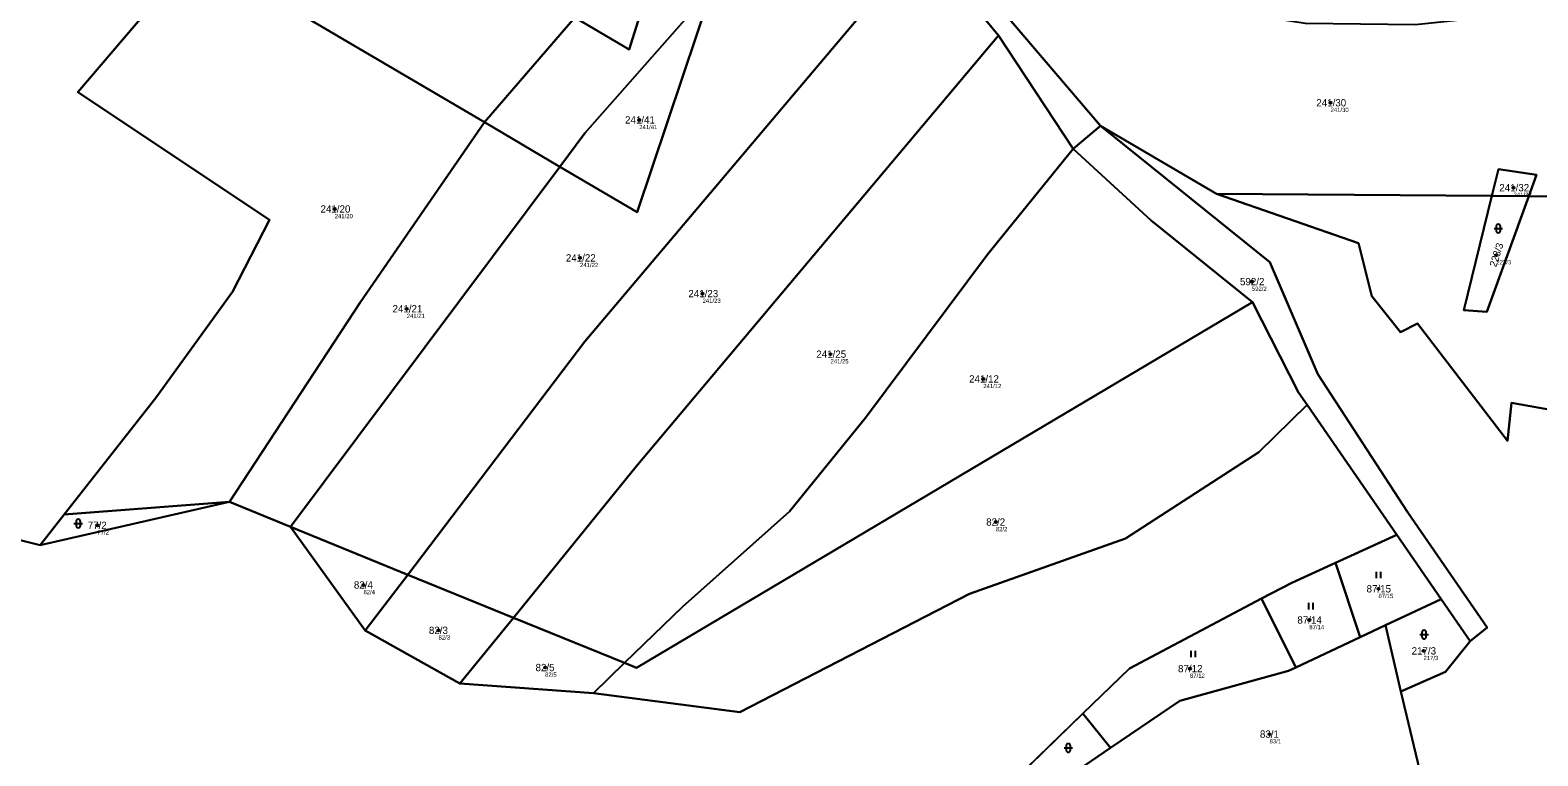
# Model space of a CAD drawing. Extents: x -766177 to -763254, y -1057727 to -1053915.
# Drawn here: x -765125.5 to -764774.5, y -1057477.4 to -1057308.4 of the extents above; entities that cross this region are included whole.
import ezdxf

# ---------------------------------------------------------------- set-up
doc = ezdxf.new("R2010")
doc.units = 0
for name, color, linetype in [('Vrstva 1', 7, 'Continuous'), ('Vrstva 2', 7, 'Continuous'), ('Vrstva 3', 7, 'Continuous'), ('Vrstva 50', 7, 'Continuous'), ('Vrstva 51', 7, 'Continuous')]:
    doc.layers.add(name, color=color, linetype=linetype)

msp = doc.modelspace()

# ---------------------------------------------------------------- linework, layer by layer
at = {"layer": 'Vrstva 1'}
for p, q in [((-764876.27, -1057330.63), (-764922.39, -1057276.56)), ((-764900.05, -1057309.6), (-764917.91, -1057287.93)), ((-765086.75, -1057290.32), (-765019.75, -1057329.82)), ((-765019.75, -1057329.82), (-764998.7, -1057305.43)), ((-764882.68, -1057336.02), (-764900.05, -1057309.6)), ((-765002.19, -1057340.18), (-765019.75, -1057329.82)), ((-764882.68, -1057336.02), (-764876.27, -1057330.63)), ((-764849.27, -1057346.5), (-764876.27, -1057330.63)), ((-765064.89, -1057424.12), (-765002.19, -1057340.18)), ((-764785.18, -1057346.97), (-764849.27, -1057346.5)), ((-764776.59, -1057347.03), (-764785.18, -1057346.97)), ((-764807.31, -1057425.97), (-764828.22, -1057395.63)), ((-765123.19, -1057428.35), (-765079.08, -1057418.23)), ((-765079.08, -1057418.23), (-765117.57, -1057421.2)), ((-765064.89, -1057424.12), (-765079.08, -1057418.23)), ((-765117.57, -1057421.2), (-765123.19, -1057428.35)), ((-765064.89, -1057424.12), (-765047.51, -1057448.26)), ((-765037.61, -1057435.23), (-765064.89, -1057424.12)), ((-764821.57, -1057432.45), (-764807.31, -1057425.97)), ((-764797.01, -1057440.9), (-764807.31, -1057425.97)), ((-764815.84, -1057449.77), (-764821.57, -1057432.45)), ((-765037.61, -1057435.23), (-765047.51, -1057448.26)), ((-765012.98, -1057445.26), (-765037.61, -1057435.23)), ((-764830.79, -1057456.83), (-764838.8, -1057440.81)), ((-764809.98, -1057447.01), (-764797.01, -1057440.9)), ((-764790.26, -1057450.69), (-764797.01, -1057440.9)), ((-765025.45, -1057460.61), (-765012.98, -1057445.26)), ((-764987.11, -1057455.79), (-765012.98, -1057445.26)), ((-765047.51, -1057448.26), (-765025.45, -1057460.61)), ((-764815.84, -1057449.77), (-764830.79, -1057456.83)), ((-764809.98, -1057447.01), (-764815.84, -1057449.77)), ((-764806.34, -1057462.41), (-764809.98, -1057447.01)), ((-764994.34, -1057462.8), (-764987.11, -1057455.79)), ((-765025.45, -1057460.61), (-764994.34, -1057462.8)), ((-764801.59, -1057482.52), (-764806.34, -1057462.41)), ((-764903.9, -1057490.42), (-764880.38, -1057467.6)), ((-764880.38, -1057467.6), (-764873.98, -1057475.6)), ((-764873.98, -1057475.6), (-764884.28, -1057482.63))]:
    msp.add_line(p, q, dxfattribs=at)
for points in [[(-764998.7, -1057305.43), (-764986.08, -1057312.85), (-764975.18, -1057278.18)], [(-765037.61, -1057435.23), (-764996.36, -1057380.92), (-764917.91, -1057287.93)], [(-765117.57, -1057421.2), (-765096.23, -1057394.04), (-765078.39, -1057369.34), (-765069.81, -1057352.56), (-765114.44, -1057322.78), (-765086.75, -1057290.32)], [(-764966.7, -1057298.67), (-764984.2, -1057350.79), (-765002.19, -1057340.18)], [(-764966.7, -1057298.67), (-764996.34, -1057332.34), (-765002.19, -1057340.18)], [(-765012.98, -1057445.26), (-764984.38, -1057410.02), (-764900.05, -1057309.6)], [(-765079.08, -1057418.23), (-765048.71, -1057371.8), (-765019.75, -1057329.82)], [(-764876.27, -1057330.63), (-764836.9, -1057362.45), (-764825.69, -1057388.55), (-764804.78, -1057420.77), (-764786.27, -1057447.55), (-764790.26, -1057450.69)], [(-764987.11, -1057455.79), (-764973.65, -1057442.75), (-764948.7, -1057420.51), (-764931.04, -1057398.68), (-764902.6, -1057360.62), (-764882.68, -1057336.02)], [(-764882.68, -1057336.02), (-764864.48, -1057352.68), (-764840.93, -1057371.77)], [(-764785.18, -1057346.97), (-764783.65, -1057340.72), (-764774.8, -1057342.1), (-764776.59, -1057347.03)], [(-764755.4, -1057399.73), (-764780.63, -1057395.22), (-764781.54, -1057404.07), (-764802.49, -1057376.7), (-764806.46, -1057378.71), (-764813.12, -1057370.35), (-764816.27, -1057358), (-764849.27, -1057346.5)], [(-764776.59, -1057347.03), (-764786.38, -1057374.02), (-764791.71, -1057373.58), (-764785.18, -1057346.97)], [(-764739.69, -1057350.49), (-764743.65, -1057347.27), (-764776.59, -1057347.03)], [(-764840.93, -1057371.77), (-764984.31, -1057456.93), (-764987.11, -1057455.79)], [(-764840.93, -1057371.77), (-764830.2, -1057392.76), (-764828.22, -1057395.63)], [(-765123.19, -1057428.35), (-765142.95, -1057423.38), (-765198.86, -1057384.72)], [(-764828.22, -1057395.63), (-764839.45, -1057406.67), (-764870.48, -1057426.83), (-764906.81, -1057439.73), (-764960.27, -1057467.29), (-764994.34, -1057462.8)], [(-764838.8, -1057440.81), (-764831.78, -1057437.09), (-764821.57, -1057432.45)], [(-764880.38, -1057467.6), (-764869.56, -1057457.1), (-764838.8, -1057440.81)], [(-764790.26, -1057450.69), (-764795.98, -1057457.9), (-764806.34, -1057462.41)], [(-764830.79, -1057456.83), (-764832.51, -1057457.64), (-764857.84, -1057464.6), (-764873.98, -1057475.6)]]:
    msp.add_lwpolyline(points, dxfattribs=at)
at = {"layer": 'Vrstva 3'}
for p, q in [((-764784.681, -1057354.581), (-764782.679, -1057354.581)), ((-764784.181, -1057354.081), (-764784.181, -1057355.082)), ((-764783.179, -1057355.082), (-764783.179, -1057354.081)), ((-765115.311, -1057423.301), (-765113.309, -1057423.301)), ((-765114.811, -1057422.801), (-765114.811, -1057423.802)), ((-765113.809, -1057423.802), (-765113.809, -1057422.801)), ((-764812.011, -1057436.04), (-764812.011, -1057434.54)), ((-764811.01, -1057436.04), (-764811.01, -1057434.54)), ((-764827.821, -1057443.32), (-764827.821, -1057441.82)), ((-764826.82, -1057443.32), (-764826.82, -1057441.82)), ((-764801.961, -1057449.191), (-764799.959, -1057449.191)), ((-764801.461, -1057448.691), (-764801.461, -1057449.692)), ((-764800.459, -1057449.692), (-764800.459, -1057448.691)), ((-764855.171, -1057454.48), (-764855.171, -1057452.98)), ((-764854.17, -1057454.48), (-764854.17, -1057452.98)), ((-764884.801, -1057475.601), (-764882.799, -1057475.601)), ((-764884.301, -1057475.101), (-764884.301, -1057476.102)), ((-764883.299, -1057476.102), (-764883.299, -1057475.101))]:
    msp.add_line(p, q, dxfattribs=at)
for centre, start, end in [((-764783.68, -1057354.0809), 0, 180), ((-764783.68, -1057355.0809), 180, 359.9878861), ((-765114.31, -1057422.8009), 0, 180), ((-765114.31, -1057423.8009), 180, 359.9878861), ((-764800.96, -1057448.6909), 0, 180), ((-764800.96, -1057449.6909), 180, 359.9878861), ((-764883.8, -1057475.1009), 0, 180), ((-764883.8, -1057476.1009), 180, 359.9878861)]:
    msp.add_arc(centre, 0.5, start, end, dxfattribs=at)
at = {"layer": 'Vrstva 50'}
for centre in [(-764822.75, -1057325.27994), (-764983.7, -1057329.27994), (-764780.14, -1057345.06994), (-765054.6, -1057350.02994), (-764997.48, -1057361.41994), (-764784.14, -1057360.77994), (-764968.96, -1057369.74994), (-764841.05, -1057366.94994), (-765037.84, -1057373.27994), (-764939.17, -1057383.84994), (-764903.6, -1057389.61994), (-765109.87, -1057423.72994), (-764900.68, -1057422.95994), (-765047.9, -1057437.61994), (-764811.58, -1057438.51994), (-764827.69, -1057445.78994), (-765030.43, -1057448.19994), (-764801.09, -1057452.97994), (-765005.61, -1057456.85994), (-764855.48, -1057457.10994), (-764836.94, -1057472.36994)]:
    msp.add_circle(centre, 0.25, dxfattribs=at)
at = {"layer": 'Vrstva 51'}
for points in [[(-764951.49, -1057253.35), (-764937.29, -1057265.26), (-764917.91, -1057287.93), (-764900.05, -1057309.6), (-764882.68, -1057336.02), (-764876.27, -1057330.63), (-764922.39, -1057276.56), (-764933.09, -1057264.01), (-764950.28, -1057249.75)], [(-764951.49, -1057253.35), (-764952.56, -1057252.46), (-764975.18, -1057278.18), (-764986.08, -1057312.85), (-764998.7, -1057305.43), (-765019.75, -1057329.82), (-765002.19, -1057340.18), (-764996.34, -1057332.34), (-764966.7, -1057298.67)], [(-765086.75, -1057290.32), (-765019.75, -1057329.82), (-764998.7, -1057305.43), (-765065.93, -1057265.91)], [(-764996.36, -1057380.92), (-764917.91, -1057287.93), (-764937.29, -1057265.26), (-764966.7, -1057298.67), (-764984.2, -1057350.79), (-765002.19, -1057340.18), (-765064.89, -1057424.12), (-765037.61, -1057435.23)], [(-765078.39, -1057369.34), (-765069.81, -1057352.56), (-765114.44, -1057322.78), (-765086.75, -1057290.32), (-765118.25, -1057271.74), (-765150.88, -1057311.82), (-765192.69, -1057371.46), (-765198.86, -1057384.72), (-765142.95, -1057423.38), (-765123.19, -1057428.35), (-765117.57, -1057421.2), (-765096.23, -1057394.04)], [(-764986.08, -1057312.85), (-764975.18, -1057278.18), (-764998.7, -1057305.43)], [(-764755.14, -1057302.1), (-764802.96, -1057307.13), (-764828.56, -1057306.85), (-764848.07, -1057303.89), (-764887.78, -1057292.31), (-764922.39, -1057276.56), (-764876.27, -1057330.63), (-764849.27, -1057346.5), (-764785.18, -1057346.97), (-764783.65, -1057340.72), (-764774.8, -1057342.1), (-764776.59, -1057347.03), (-764743.65, -1057347.27), (-764739.69, -1057350.49), (-764747.15, -1057333.46)], [(-764900.05, -1057309.6), (-764917.91, -1057287.93), (-764996.36, -1057380.92), (-765037.61, -1057435.23), (-765012.98, -1057445.26), (-764984.38, -1057410.02)], [(-765048.71, -1057371.8), (-765019.75, -1057329.82), (-765086.75, -1057290.32), (-765114.44, -1057322.78), (-765069.81, -1057352.56), (-765078.39, -1057369.34), (-765096.23, -1057394.04), (-765117.57, -1057421.2), (-765079.08, -1057418.23)], [(-764996.34, -1057332.34), (-765002.19, -1057340.18), (-764984.2, -1057350.79), (-764966.7, -1057298.67)], [(-764948.7, -1057420.51), (-764931.04, -1057398.68), (-764902.6, -1057360.62), (-764882.68, -1057336.02), (-764900.05, -1057309.6), (-764984.38, -1057410.02), (-765012.98, -1057445.26), (-764987.11, -1057455.79), (-764973.65, -1057442.75)], [(-765002.19, -1057340.18), (-765019.75, -1057329.82), (-765048.71, -1057371.8), (-765079.08, -1057418.23), (-765064.89, -1057424.12)], [(-764840.93, -1057371.77), (-764830.2, -1057392.76), (-764828.22, -1057395.63), (-764807.31, -1057425.97), (-764797.01, -1057440.9), (-764790.26, -1057450.69), (-764786.27, -1057447.55), (-764804.78, -1057420.77), (-764825.69, -1057388.55), (-764836.9, -1057362.45), (-764876.27, -1057330.63), (-764882.68, -1057336.02), (-764864.48, -1057352.68)], [(-764882.68, -1057336.02), (-764902.6, -1057360.62), (-764931.04, -1057398.68), (-764948.7, -1057420.51), (-764973.65, -1057442.75), (-764987.11, -1057455.79), (-764984.31, -1057456.93), (-764840.93, -1057371.77), (-764864.48, -1057352.68)], [(-764785.18, -1057346.97), (-764776.59, -1057347.03), (-764774.8, -1057342.1), (-764783.65, -1057340.72)], [(-764732.1, -1057381.53), (-764735, -1057361.74), (-764739.69, -1057350.49), (-764743.65, -1057347.27), (-764776.59, -1057347.03), (-764786.38, -1057374.02), (-764791.71, -1057373.58), (-764785.18, -1057346.97), (-764849.27, -1057346.5), (-764816.27, -1057358), (-764813.12, -1057370.35), (-764806.46, -1057378.71), (-764802.49, -1057376.7), (-764781.54, -1057404.07), (-764780.63, -1057395.22), (-764755.4, -1057399.73), (-764754.5, -1057378.44)], [(-764776.59, -1057347.03), (-764785.18, -1057346.97), (-764791.71, -1057373.58), (-764786.38, -1057374.02)], [(-764984.31, -1057456.93), (-764987.11, -1057455.79), (-764994.34, -1057462.8), (-764960.27, -1057467.29), (-764906.81, -1057439.73), (-764870.48, -1057426.83), (-764839.45, -1057406.67), (-764828.22, -1057395.63), (-764830.2, -1057392.76), (-764840.93, -1057371.77)], [(-765079.08, -1057418.23), (-765117.57, -1057421.2), (-765123.19, -1057428.35)], [(-765037.61, -1057435.23), (-765064.89, -1057424.12), (-765047.51, -1057448.26)], [(-764807.31, -1057425.97), (-764821.57, -1057432.45), (-764815.84, -1057449.77), (-764809.98, -1057447.01), (-764797.01, -1057440.9)], [(-764815.84, -1057449.77), (-764821.57, -1057432.45), (-764831.78, -1057437.09), (-764838.8, -1057440.81), (-764830.79, -1057456.83)], [(-765012.98, -1057445.26), (-765037.61, -1057435.23), (-765047.51, -1057448.26), (-765025.45, -1057460.61)], [(-764830.79, -1057456.83), (-764838.8, -1057440.81), (-764869.56, -1057457.1), (-764880.38, -1057467.6), (-764873.98, -1057475.6), (-764857.84, -1057464.6), (-764832.51, -1057457.64)], [(-764797.01, -1057440.9), (-764809.98, -1057447.01), (-764806.34, -1057462.41), (-764795.98, -1057457.9), (-764790.26, -1057450.69)], [(-764987.11, -1057455.79), (-765012.98, -1057445.26), (-765025.45, -1057460.61), (-764994.34, -1057462.8)], [(-764873.98, -1057475.6), (-764884.28, -1057482.63), (-764881.69, -1057492.12), (-764851.45, -1057486.26), (-764801.59, -1057482.52), (-764806.34, -1057462.41), (-764809.98, -1057447.01), (-764815.84, -1057449.77), (-764830.79, -1057456.83), (-764832.51, -1057457.64), (-764857.84, -1057464.6)], [(-764884.28, -1057482.63), (-764873.98, -1057475.6), (-764880.38, -1057467.6), (-764903.9, -1057490.42)]]:
    msp.add_lwpolyline(points, close=True, dxfattribs=at)
for points in [[(-764755.4, -1057399.73), (-764780.63, -1057395.22), (-764781.54, -1057404.07), (-764802.49, -1057376.7), (-764806.46, -1057378.71), (-764813.12, -1057370.35), (-764816.27, -1057358), (-764849.27, -1057346.5), (-764876.27, -1057330.63), (-764836.9, -1057362.45), (-764825.69, -1057388.55), (-764804.78, -1057420.77), (-764786.27, -1057447.55), (-764790.26, -1057450.69), (-764795.98, -1057457.9), (-764806.34, -1057462.41), (-764801.59, -1057482.52)], [(-764903.9, -1057490.42), (-764880.38, -1057467.6), (-764869.56, -1057457.1), (-764838.8, -1057440.81), (-764831.78, -1057437.09), (-764821.57, -1057432.45), (-764807.31, -1057425.97), (-764828.22, -1057395.63), (-764839.45, -1057406.67), (-764870.48, -1057426.83), (-764906.81, -1057439.73), (-764960.27, -1057467.29), (-764994.34, -1057462.8), (-765025.45, -1057460.61), (-765047.51, -1057448.26), (-765064.89, -1057424.12), (-765079.08, -1057418.23), (-765123.19, -1057428.35), (-765142.95, -1057423.38)]]:
    msp.add_lwpolyline(points, dxfattribs=at)

# ---------------------------------------------------------------- texts
at = {"layer": 'Vrstva 2'}
for s, p in [('241/30', (-764826.055, -1057326.13)), ('241/41', (-764987.005, -1057330.13)), ('241/32', (-764783.445, -1057345.92)), ('241/20', (-765057.905, -1057350.88)), ('241/22', (-765000.785, -1057362.27)), ('592/2', (-764843.823, -1057367.8)), ('241/23', (-764972.265, -1057370.6)), ('241/21', (-765041.145, -1057374.13)), ('241/25', (-764942.475, -1057384.7)), ('241/12', (-764906.905, -1057390.47)), ('82/2', (-764902.921, -1057423.81)), ('77/2', (-765112.111, -1057424.58)), ('82/4', (-765050.141, -1057438.47)), ('87/15', (-764814.353, -1057439.37)), ('87/14', (-764830.463, -1057446.64)), ('82/3', (-765032.671, -1057449.05)), ('217/3', (-764803.863, -1057453.83)), ('82/5', (-765007.851, -1057457.71)), ('87/12', (-764858.253, -1057457.96)), ('83/1', (-764839.181, -1057473.22))]:
    msp.add_text(s, height=1.699998, dxfattribs=at).set_placement(p)
msp.add_text('223/3', height=1.699998, rotation=72, dxfattribs=at).set_placement((-764784.188, -1057363.68))
at = {"layer": 'Vrstva 50'}
for s, p in [('241/30', (-764822.75, -1057327.436)), ('241/41', (-764983.7, -1057331.436)), ('241/32', (-764780.14, -1057347.226)), ('241/20', (-765054.6, -1057352.186)), ('241/22', (-764997.48, -1057363.576)), ('223/3', (-764784.14, -1057362.936)), ('592/2', (-764841.05, -1057369.106)), ('241/23', (-764968.96, -1057371.906)), ('241/21', (-765037.84, -1057375.436)), ('241/25', (-764939.17, -1057386.006)), ('241/12', (-764903.6, -1057391.776)), ('77/2', (-765109.87, -1057425.886)), ('82/2', (-764900.68, -1057425.116)), ('82/4', (-765047.9, -1057439.776)), ('87/15', (-764811.58, -1057440.676)), ('82/3', (-765030.43, -1057450.356)), ('87/14', (-764827.69, -1057447.946)), ('217/3', (-764801.09, -1057455.136)), ('82/5', (-765005.61, -1057459.016)), ('87/12', (-764855.48, -1057459.266)), ('83/1', (-764836.94, -1057474.526))]:
    msp.add_text(s, height=0.999996, dxfattribs=at).set_placement(p)

doc.saveas('drawing.dxf')
